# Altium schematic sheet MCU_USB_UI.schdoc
size 127 x 101 mm
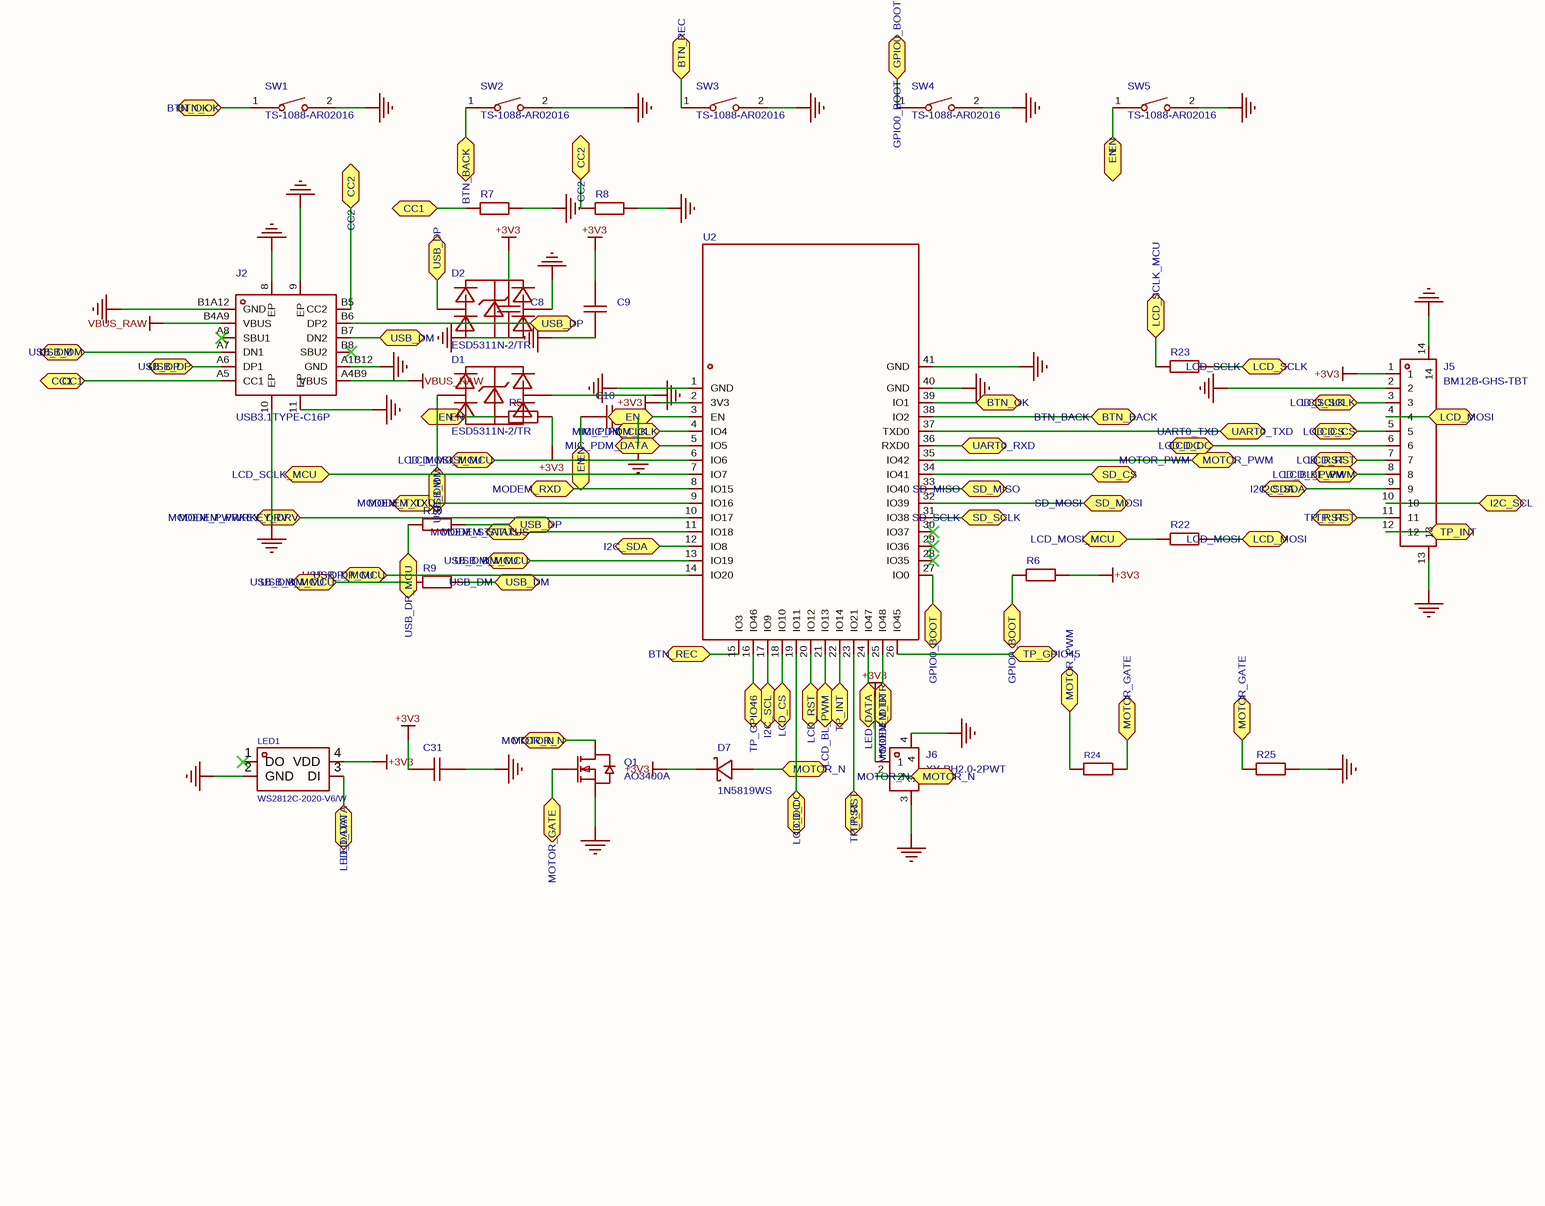
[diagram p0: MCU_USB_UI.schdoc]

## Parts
C8  (no value)  [C0805]
C9  (no value)  [C0402]
C10  (no value)  [C0402]
C31  (no value)  [C0402]
D1  ESD5311N-2/TR  [X1-DFN1006-2_L1.0-W0.6_ESD5311N-2-TR]
D2  ESD5311N-2/TR  [X1-DFN1006-2_L1.0-W0.6_ESD5311N-2-TR]
D7  1N5819WS  [SOD-323_L1.8-W1.3-LS2.5-RD]
J2  USB3.1TYPE-C16P  [USB-C-SMD_TYPE-C-16PIN]
J5  BM12B-GHS-TBT  [CONN-SMD_12P-P1.25_BM10B-GHS-TBT-LF-SN]
J6  XY-PH2.0-2PWT  [CONN-SMD_XY-PH2.0-2PWT]
LED1  WS2812C-2020-V6/W  [LED-SMD_4P-L2.0-W2.0-TL_WS2812B-2020]
Q1  AO3400A  [SOT-23-3_L2.9-W1.3-P1.90-LS2.4-BR]
R5  (no value)  [R0402]
R6  (no value)  [R0402]
R7  (no value)  [R0402]
R8  (no value)  [R0402]
R9  (no value)  [R0402]
R10  (no value)  [R0402]
R22  (no value)  [R0402]
R23  (no value)  [R0402]
R24  (no value)  [R0402]
R25  (no value)  [R0402]
SW1  TS-1088-AR02016  [SW-SMD_L3.9-W3.0-P4.45]
SW2  TS-1088-AR02016  [SW-SMD_L3.9-W3.0-P4.45]
SW3  TS-1088-AR02016  [SW-SMD_L3.9-W3.0-P4.45]
SW4  TS-1088-AR02016  [SW-SMD_L3.9-W3.0-P4.45]
SW5  TS-1088-AR02016  [SW-SMD_L3.9-W3.0-P4.45]
U2  (no value)  [WIRELM-SMD_ESP32-S3-WROOM-1]

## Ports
BTN_BACK (bidir), BTN_OK (bidir), BTN_REC (bidir), CC1 (bidir), CC2 (bidir), EN (bidir), GPIO0_BOOT (bidir), I2C_SCL (bidir), I2C_SDA (bidir), LCD_BL_PWM (bidir), LCD_CS (bidir), LCD_DC (bidir), LCD_MOSI (bidir), LCD_MOSI_MCU (bidir), LCD_RST (bidir), LCD_SCLK (bidir), LCD_SCLK_MCU (bidir), LED_DATA (bidir), MIC_PDM_CLK (bidir), MIC_PDM_DATA (bidir), MODEM_DTR (bidir), MODEM_PWRKEY_DRV (bidir), MODEM_RXD (bidir), MODEM_STATUS (bidir), MODEM_TXD (bidir), MOTOR_GATE (bidir), MOTOR_N (bidir), MOTOR_PWM (bidir), SD_CS (bidir), SD_MISO (bidir), SD_MOSI (bidir), SD_SCLK (bidir), TP_GPIO45 (bidir), TP_GPIO46 (bidir), TP_INT (bidir), TP_RST (bidir), UART0_RXD (bidir), UART0_TXD (bidir), USB_DM (bidir), USB_DM_MCU (bidir), USB_DP (bidir), USB_DP_MCU (bidir)

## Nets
+3V3: C8.1 C9.1 C31.1 D7.1(K) J5.1 J6.1 LED1.4(VDD) R5.2 R6.2 U2.2(3V3)
GND: C8.2 C9.2 C10.2 C31.2 D1.2 D2.2 J2.8(EP) J2.9(EP) J2.10(EP) J2.11(EP) J2.A1B12(GND) J2.B1A12(GND) J5.2 J5.13 J5.14 J6.3 J6.4 LED1.2(GND) Q1.2(S) R7.2 R8.2 R25.2 SW1.2 SW2.2 SW3.2 SW4.2 SW5.2 U2.1(GND) U2.40(GND) U2.41(GND)
VBUS_RAW: J2.A4B9(VBUS) J2.B4A9(VBUS)
BTN_BACK: SW2.1 U2.38(IO2) ; port BTN_BACK
BTN_OK: SW1.1 U2.39(IO1) ; port BTN_OK
BTN_REC: SW3.1 U2.15(IO3) ; port BTN_REC
CC1: J2.A5(CC1) R7.1 ; port CC1
CC2: J2.B5(CC2) R8.1 ; port CC2
EN: C10.1 R5.1 SW5.1 U2.3(EN) ; port EN
GPIO0_BOOT: R6.1 SW4.1 U2.27(IO0) ; port GPIO0_BOOT
I2C_SCL: J5.10 U2.17(IO9) ; port I2C_SCL
I2C_SDA: J5.9 U2.12(IO8) ; port I2C_SDA
LCD_BL_PWM: J5.8 U2.21(IO13) ; port LCD_BL_PWM
LCD_CS: J5.5 U2.18(IO10) ; port LCD_CS
LCD_DC: J5.6 U2.19(IO11) ; port LCD_DC
LCD_MOSI: J5.4 R22.2 ; port LCD_MOSI
LCD_MOSI_MCU: R22.1 U2.6(IO6) ; port LCD_MOSI_MCU
LCD_RST: J5.7 U2.20(IO12) ; port LCD_RST
LCD_SCLK: J5.3 R23.2 ; port LCD_SCLK
LCD_SCLK_MCU: R23.1 U2.7(IO7) ; port LCD_SCLK_MCU
LED_DATA: LED1.3(DI) U2.24(IO47) ; port LED_DATA
MIC_PDM_CLK: U2.4(IO4) ; port MIC_PDM_CLK
MIC_PDM_DATA: U2.5(IO5) ; port MIC_PDM_DATA
MODEM_DTR: U2.25(IO48) ; port MODEM_DTR
MODEM_PWRKEY_DRV: U2.10(IO17) ; port MODEM_PWRKEY_DRV
MODEM_RXD: U2.8(IO15) ; port MODEM_RXD
MODEM_STATUS: U2.11(IO18) ; port MODEM_STATUS
MODEM_TXD: U2.9(IO16) ; port MODEM_TXD
MOTOR_GATE: Q1.1(G) R24.2 R25.1 ; port MOTOR_GATE
MOTOR_N: D7.2(A) J6.2 Q1.3(D) ; port MOTOR_N
MOTOR_PWM: R24.1 U2.35(IO42) ; port MOTOR_PWM
SD_CS: U2.34(IO41) ; port SD_CS
SD_MISO: U2.33(IO40) ; port SD_MISO
SD_MOSI: U2.32(IO39) ; port SD_MOSI
SD_SCLK: U2.31(IO38) ; port SD_SCLK
TP_GPIO45: U2.26(IO45) ; port TP_GPIO45
TP_GPIO46: U2.16(IO46) ; port TP_GPIO46
TP_INT: J5.12 U2.22(IO14) ; port TP_INT
TP_RST: J5.11 U2.23(IO21) ; port TP_RST
UART0_RXD: U2.36(RXD0) ; port UART0_RXD
UART0_TXD: U2.37(TXD0) ; port UART0_TXD
USB_DM: D1.1 J2.A7(DN1) J2.B7(DN2) R9.2 ; port USB_DM
USB_DM_MCU: R9.1 U2.13(IO19) ; port USB_DM_MCU
USB_DP: D2.1 J2.A6(DP1) J2.B6(DP2) R10.2 ; port USB_DP
USB_DP_MCU: R10.1 U2.14(IO20) ; port USB_DP_MCU

Not connected (* = marked no-connect by the designer): J2 A8(SBU1)* B8(SBU2)*; LED1 1(DO)*; U2 28(IO35)* 29(IO36)* 30(IO37)*

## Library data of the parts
C8 = GRM21BR61H106KE43L: Manufacturer: muRata(村田); Add into BOM: yes; ModelId: 1ba041120af144c991958decab20d2410819f05c4eef4c71ace90d822a990e87; ModelName: C0805_L2.0-W1.3-H1.3; ModelTransform: 78.74,51.181,0,0,0,0,0,0.0005,0
C9 C31 = CL05B104KO5NNNC: Manufacturer: SAMSUNG(三星); Add into BOM: yes; ModelId: 36a51122f27c49738f86b3bfa98863e00819f05c4eef4c71ace90d822a990e87; ModelName: C0402_L1.0-W0.5-H0.5; ModelTransform: 39.37,19.685,0,0,0,0,0,0,0
C10 = CL05A105KA5NQNC: Manufacturer: SAMSUNG(三星); Add into BOM: yes; ModelId: 36a51122f27c49738f86b3bfa98863e00819f05c4eef4c71ace90d822a990e87; ModelName: C0402_L1.0-W0.5-H0.5; ModelTransform: 39.37,19.685,0,0,0,0,0,0,0
D1 D2 = ESD5311N-2/TR: Manufacturer: WILLSEMI(韦尔); Add into BOM: yes
D7 = 1N5819WS_C191023: Manufacturer: Hottech(合科泰); Add into BOM: yes; ModelId: db63db13d9e342eb939127d413d6200b0819f05c4eef4c71ace90d822a990e87; ModelTransform: 104.3305,51.181,0,0,0,0,0,-0.004,0
J2 = USB3.1TYPE-C16P: Add into BOM: yes; ModelId: d9eeaf12559949358a6abfb49919ec6d0819f05c4eef4c71ace90d822a990e87; ModelTransform: 452.755,311.023,0,0,0,0,0,-52.52,-31.496
J5 = BM12B-GHS-TBT: Manufacturer: JST; Add into BOM: yes; ModelId: b51a162de4be495b8c15a5d16742ba4e0819f05c4eef4c71ace90d822a990e87; ModelTransform: 718.896,194.8815,0,0,0,0,0,-10.827,0
J6 = XY-PH2.0-2PWT: Manufacturer: XYECONN(辛译); Add into BOM: yes
LED1 = WS2812C-2020-V6/W: Manufacturer: worldsemi; Add into BOM: yes; ModelId: ec3f1773c2c342958c28fcec35b8a2470819f05c4eef4c71ace90d822a990e87; ModelName: LED-SMD_4P-L2.0-W2.0-H0.8-TL_WS2812B-2020; ModelTransform: 78.74,78.74,0,0,0,0,0.001,0.005,0
Q1 = AO3400A_C20917: Manufacturer: AOS; Add into BOM: yes; ModelId: c62791f0466c4ae2a892c056b845b0ca0819f05c4eef4c71ace90d822a990e87; ModelName: SOT-23-3P_L2.9-W1.3-H1.0-LS2.4-P0.95; ModelTransform: 98.425,114.173,0,180,0,0,0.0005,-0.0005,0
R5 R6 = 0402WGF1002TCE: Manufacturer: UNI-ROYAL(厚声); Add into BOM: yes; ModelId: 98c88bc2b9094f218f3a3e30a70127380819f05c4eef4c71ace90d822a990e87; ModelName: R0402_L1.0-W0.5-H0.4; ModelTransform: 39.37,19.685,0,0,0,0,0,0,0
R7 R8 = 0402WGF5101TCE: Manufacturer: UNI-ROYAL(厚声); Add into BOM: yes; ModelId: 98c88bc2b9094f218f3a3e30a70127380819f05c4eef4c71ace90d822a990e87; ModelName: R0402_L1.0-W0.5-H0.4; ModelTransform: 39.37,19.685,0,0,0,0,0,0,0
R9 R10 R22 R23 = 0402WGF220JTCE: Manufacturer: UNI-ROYAL(厚声); Add into BOM: yes; ModelId: 98c88bc2b9094f218f3a3e30a70127380819f05c4eef4c71ace90d822a990e87; ModelName: R0402_L1.0-W0.5-H0.4; ModelTransform: 39.37,19.685,0,0,0,0,0,0,0
R24 = 0402WGF1000TCE: Manufacturer: UNI-ROYAL(厚声); Add into BOM: yes; ModelId: 98c88bc2b9094f218f3a3e30a70127380819f05c4eef4c71ace90d822a990e87; ModelName: R0402_L1.0-W0.5-H0.4; ModelTransform: 39.37,19.685,0,0,0,0,0,0,0
R25 = 0402WGF1003TCE: Manufacturer: UNI-ROYAL(厚声); Add into BOM: yes; ModelId: 98c88bc2b9094f218f3a3e30a70127380819f05c4eef4c71ace90d822a990e87; ModelName: R0402_L1.0-W0.5-H0.4; ModelTransform: 39.37,19.685,0,0,0,0,0,0,0
SW1-SW5 = TS-1088-AR02016: Manufacturer: XUNPU(讯普); Add into BOM: yes; ModelId: b26698b69f274ffabef8a26c7d0e5dd10819f05c4eef4c71ace90d822a990e87; ModelName: SW-SMD_L3.9-W2.9-H2.0-LS4.8; ModelTransform: 188.976,114.174,0,0,0,0,0,0,0
U2 = ESP32-S3-WROOM-1-N16R8: Manufacturer: ESPRESSIF(乐鑫); Symbol: ESP32-S3-WROOM-1(N16R8); Add into BOM: yes; 3D Model: 481f5bdfc076422c9bb3c23c3ada9c170819f05c4eef4c71ace90d822a990e87; 3D Model Transform: 708.73866,1003.97437,0,0,0,0,0,143.7,0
